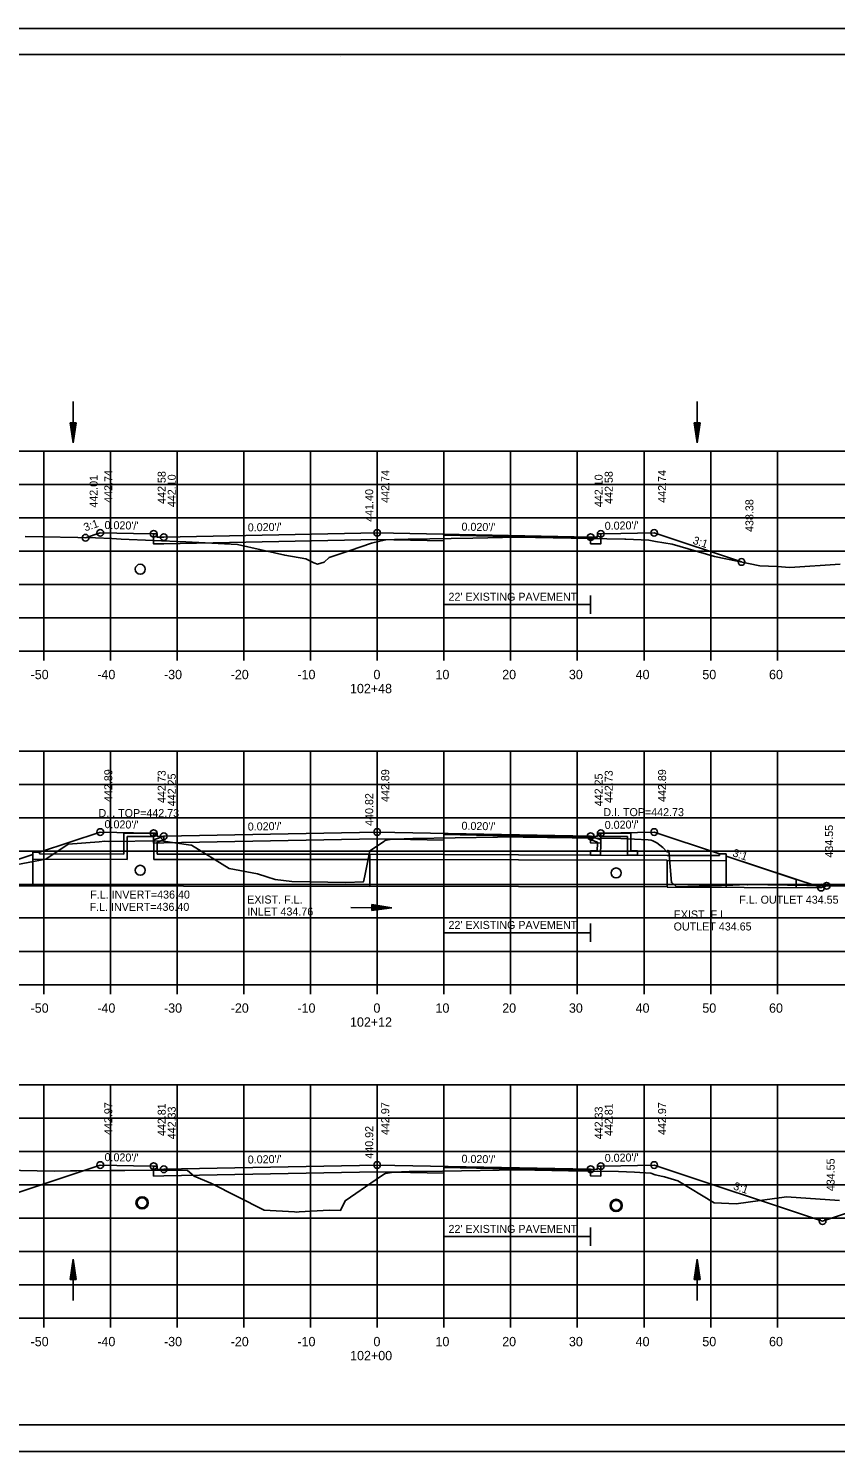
# Model space of a CAD drawing. Extents: x 1538688 to 1540766, y 656250 to 671912.
# Drawn here: x 1538805.9 to 1538926.9, y 656551.2 to 656764.6 of the extents above; entities that cross this region are included whole.
import ezdxf

# ---------------------------------------------------------------- set-up
doc = ezdxf.new("R2010")
doc.units = 0
doc.layers.add('19', color=7, linetype='Continuous')

msp = doc.modelspace()

# ---------------------------------------------------------------- linework, layer by layer
at = {"layer": '19'}
for p, q in [((1538687.78, 656764.57), (1539021.11, 656764.57)), ((1538700.18, 656760.68), (1539016.36, 656760.68)), ((1538852.7, 656760.42), (1538852.7, 656760.42)), ((1538852.7, 656760.42), (1538852.7, 656760.42)), ((1538812.62, 656708.66), (1538812.62, 656702.47)), ((1538906.16, 656708.66), (1538906.16, 656702.47)), ((1538812.17, 656705.47), (1538812.62, 656702.47)), ((1538812.17, 656705.47), (1538813.07, 656705.47)), ((1538812.25, 656705.47), (1538812.62, 656702.97)), ((1538812.33, 656705.47), (1538812.62, 656703.49)), ((1538812.4, 656705.47), (1538812.62, 656703.99)), ((1538812.48, 656705.47), (1538812.62, 656704.5)), ((1538812.55, 656705.47), (1538812.62, 656705)), ((1538813.07, 656705.47), (1538812.62, 656702.47)), ((1538812.77, 656705.47), (1538812.62, 656704.5)), ((1538812.92, 656705.47), (1538812.62, 656703.49)), ((1538813, 656705.47), (1538812.62, 656702.97)), ((1538812.85, 656705.47), (1538812.62, 656703.99)), ((1538812.7, 656705.47), (1538812.62, 656705)), ((1538905.71, 656705.47), (1538906.16, 656702.47)), ((1538905.71, 656705.47), (1538906.61, 656705.47)), ((1538905.79, 656705.47), (1538906.16, 656702.97)), ((1538905.86, 656705.47), (1538906.16, 656703.49)), ((1538905.94, 656705.47), (1538906.16, 656703.99)), ((1538906.02, 656705.47), (1538906.16, 656704.5)), ((1538906.09, 656705.47), (1538906.16, 656705)), ((1538906.61, 656705.47), (1538906.16, 656702.47)), ((1538906.31, 656705.47), (1538906.16, 656704.5)), ((1538906.46, 656705.47), (1538906.16, 656703.49)), ((1538906.54, 656705.47), (1538906.16, 656702.97)), ((1538906.39, 656705.47), (1538906.16, 656703.99)), ((1538906.23, 656705.47), (1538906.16, 656705)), ((1538718.18, 656701.22), (1538998.18, 656701.22)), ((1538808.18, 656671.22), (1538808.18, 656701.22)), ((1538818.18, 656671.22), (1538818.18, 656701.22)), ((1538828.18, 656671.22), (1538828.18, 656701.22)), ((1538838.18, 656671.22), (1538838.18, 656701.22)), ((1538848.18, 656671.22), (1538848.18, 656701.22)), ((1538858.18, 656671.22), (1538858.18, 656701.22)), ((1538868.18, 656671.22), (1538868.18, 656701.22)), ((1538878.18, 656671.22), (1538878.18, 656701.22)), ((1538888.18, 656671.22), (1538888.18, 656701.22)), ((1538898.18, 656671.22), (1538898.18, 656701.22)), ((1538908.18, 656671.22), (1538908.18, 656701.22)), ((1538918.18, 656671.22), (1538918.18, 656701.22)), ((1538718.18, 656696.22), (1538998.18, 656696.22)), ((1538718.18, 656691.22), (1538998.18, 656691.22)), ((1538718.18, 656686.22), (1538998.18, 656686.22)), ((1538718.18, 656681.22), (1538998.18, 656681.22)), ((1538868.17, 656679.59), (1538868.17, 656676.84)), ((1538890.17, 656679.59), (1538890.17, 656676.84)), ((1538890.17, 656678.22), (1538868.17, 656678.22)), ((1538718.18, 656676.22), (1538998.18, 656676.22)), ((1538718.18, 656671.22), (1538998.18, 656671.22)), ((1538718.18, 656671.22), (1538998.18, 656671.22)), ((1538808.18, 656669.82), (1538808.18, 656671.22)), ((1538818.18, 656669.82), (1538818.18, 656671.22)), ((1538828.18, 656669.82), (1538828.18, 656671.22)), ((1538838.18, 656669.82), (1538838.18, 656671.22)), ((1538848.18, 656669.82), (1538848.18, 656671.22)), ((1538858.18, 656669.82), (1538858.18, 656671.22)), ((1538868.18, 656669.82), (1538868.18, 656671.22)), ((1538878.18, 656669.82), (1538878.18, 656671.22)), ((1538888.18, 656669.82), (1538888.18, 656671.22)), ((1538898.18, 656669.82), (1538898.18, 656671.22)), ((1538908.18, 656669.82), (1538908.18, 656671.22)), ((1538918.18, 656669.82), (1538918.18, 656671.22)), ((1538718.18, 656656.22), (1538998.18, 656656.22)), ((1538808.18, 656621.22), (1538808.18, 656656.22)), ((1538818.18, 656621.22), (1538818.18, 656656.22)), ((1538828.18, 656621.22), (1538828.18, 656656.22)), ((1538838.18, 656621.22), (1538838.18, 656656.22)), ((1538848.18, 656621.22), (1538848.18, 656656.22)), ((1538858.18, 656621.22), (1538858.18, 656656.22)), ((1538868.18, 656621.22), (1538868.18, 656656.22)), ((1538878.18, 656621.22), (1538878.18, 656656.22)), ((1538888.18, 656621.22), (1538888.18, 656656.22)), ((1538898.18, 656621.22), (1538898.18, 656656.22)), ((1538908.18, 656621.22), (1538908.18, 656656.22)), ((1538918.18, 656621.22), (1538918.18, 656656.22)), ((1538718.18, 656651.22), (1538998.18, 656651.22)), ((1538718.18, 656646.22), (1538998.18, 656646.22)), ((1538820.18, 656643.95), (1538824.93, 656643.95)), ((1538820.18, 656642.45), (1538820.18, 656643.95)), ((1538820.68, 656642.45), (1538820.68, 656643.45)), ((1538820.68, 656643.45), (1538824.68, 656643.45)), ((1538825.01, 656643.79), (1538824.68, 656643.45)), ((1538826.18, 656643.47), (1538824.68, 656642.95)), ((1538824.68, 656642.45), (1538824.68, 656642.95)), ((1538825.01, 656643.79), (1538824.93, 656643.95)), ((1538826.18, 656642.94), (1538825.18, 656642.6)), ((1538825.18, 656642.45), (1538825.18, 656642.6)), ((1538890.19, 656643.47), (1538891.69, 656642.95)), ((1538890.19, 656642.94), (1538891.19, 656642.6)), ((1538891.19, 656642.45), (1538891.19, 656642.6)), ((1538891.35, 656643.79), (1538891.44, 656643.95)), ((1538891.35, 656643.79), (1538891.69, 656643.45)), ((1538896.19, 656643.95), (1538891.44, 656643.95)), ((1538895.69, 656643.45), (1538891.69, 656643.45)), ((1538891.69, 656642.45), (1538891.69, 656642.95)), ((1538895.69, 656642.45), (1538895.69, 656643.45)), ((1538896.19, 656642.45), (1538896.19, 656643.95)), ((1538718.18, 656641.22), (1538998.18, 656641.22)), ((1538806.58, 656640.75), (1538796.08, 656637.25)), ((1538806.58, 656641.08), (1538806.58, 656636.04)), ((1538807.58, 656641.08), (1538806.58, 656641.08)), ((1538807.58, 656641.08), (1538807.58, 656640.83)), ((1538807.58, 656640.84), (1538820.18, 656640.81)), ((1538808.84, 656640.83), (1538808.84, 656640.83)), ((1538820.18, 656642.45), (1538820.18, 656640.81)), ((1538820.18, 656640.81), (1538820.18, 656640.81)), ((1538820.68, 656642.45), (1538820.68, 656640.01)), ((1538820.68, 656640.8), (1538820.68, 656640.8)), ((1538824.68, 656642.45), (1538824.68, 656640)), ((1538825.18, 656642.46), (1538825.18, 656640.79)), ((1538825.18, 656640.79), (1538825.18, 656640.79)), ((1538825.18, 656640.79), (1538857.1, 656640.77)), ((1538857.1, 656639.98), (1538857.1, 656640.77)), ((1538891.19, 656642.45), (1538891.18, 656641.3)), ((1538891.18, 656640.64), (1538891.18, 656640.64)), ((1538891.69, 656642.45), (1538891.68, 656640.65)), ((1538891.68, 656640.64), (1538891.68, 656640.64)), ((1538895.69, 656642.45), (1538895.68, 656640.63)), ((1538895.68, 656640.63), (1538895.68, 656640.63)), ((1538896.19, 656642.45), (1538896.18, 656641.3)), ((1538896.18, 656640.62), (1538896.18, 656640.62)), ((1538901.65, 656640.61), (1538909.48, 656640.6)), ((1538909.48, 656640.85), (1538910.48, 656640.85)), ((1538909.48, 656640.85), (1538909.48, 656640.6)), ((1538910.48, 656640.85), (1538910.48, 656635.8)), ((1538910.48, 656640.51), (1538920.98, 656637.01)), ((1538806.58, 656640.05), (1538820.68, 656640.01)), ((1538820.68, 656640.01), (1538820.68, 656640.01)), ((1538824.68, 656640), (1538857.1, 656639.98)), ((1538824.68, 656640), (1538824.68, 656640)), ((1538901.65, 656639.82), (1538910.48, 656639.8)), ((1538718.18, 656636.22), (1538998.18, 656636.22)), ((1538792.57, 656636.08), (1538857.1, 656635.93)), ((1538920.98, 656637.01), (1538920.98, 656635.83)), ((1538807.84, 656636.04), (1538807.84, 656636.04)), ((1538901.65, 656635.82), (1538924.73, 656635.76)), ((1538854.21, 656632.81), (1538860.39, 656632.76)), ((1538857.4, 656633.23), (1538857.39, 656632.33)), ((1538857.39, 656632.64), (1538858.37, 656632.78)), ((1538857.39, 656632.71), (1538857.87, 656632.78)), ((1538857.39, 656632.49), (1538859.38, 656632.77)), ((1538857.39, 656632.56), (1538858.88, 656632.77)), ((1538857.39, 656632.33), (1538860.39, 656632.76)), ((1538857.39, 656632.41), (1538859.89, 656632.76)), ((1538857.4, 656633.23), (1538860.39, 656632.76)), ((1538857.4, 656633.16), (1538859.89, 656632.76)), ((1538857.4, 656633.08), (1538859.38, 656632.77)), ((1538857.4, 656633.01), (1538858.88, 656632.77)), ((1538857.4, 656632.93), (1538858.37, 656632.78)), ((1538857.4, 656632.85), (1538857.87, 656632.78)), ((1538718.18, 656631.22), (1538998.18, 656631.22)), ((1538868.17, 656630.39), (1538868.17, 656627.65)), ((1538890.17, 656630.39), (1538890.17, 656627.65)), ((1538890.17, 656629.02), (1538868.17, 656629.02)), ((1538718.18, 656626.22), (1538998.18, 656626.22)), ((1538718.18, 656621.22), (1538998.18, 656621.22)), ((1538718.18, 656621.22), (1538998.18, 656621.22)), ((1538808.18, 656619.82), (1538808.18, 656621.22)), ((1538818.18, 656619.82), (1538818.18, 656621.22)), ((1538828.18, 656619.82), (1538828.18, 656621.22)), ((1538838.18, 656619.82), (1538838.18, 656621.22)), ((1538848.18, 656619.82), (1538848.18, 656621.22)), ((1538858.18, 656619.82), (1538858.18, 656621.22)), ((1538868.18, 656619.82), (1538868.18, 656621.22)), ((1538878.18, 656619.82), (1538878.18, 656621.22)), ((1538888.18, 656619.82), (1538888.18, 656621.22)), ((1538898.18, 656619.82), (1538898.18, 656621.22)), ((1538908.18, 656619.82), (1538908.18, 656621.22)), ((1538918.18, 656619.82), (1538918.18, 656621.22)), ((1538718.18, 656606.22), (1538998.18, 656606.22)), ((1538808.18, 656571.22), (1538808.18, 656606.22)), ((1538818.18, 656571.22), (1538818.18, 656606.22)), ((1538828.18, 656571.22), (1538828.18, 656606.22)), ((1538838.18, 656571.22), (1538838.18, 656606.22)), ((1538848.18, 656571.22), (1538848.18, 656606.22)), ((1538858.18, 656571.22), (1538858.18, 656606.22)), ((1538868.18, 656571.22), (1538868.18, 656606.22)), ((1538878.18, 656571.22), (1538878.18, 656606.22)), ((1538888.18, 656571.22), (1538888.18, 656606.22)), ((1538898.18, 656571.22), (1538898.18, 656606.22)), ((1538908.18, 656571.22), (1538908.18, 656606.22)), ((1538918.18, 656571.22), (1538918.18, 656606.22)), ((1538718.18, 656601.22), (1538998.18, 656601.22)), ((1538718.18, 656596.22), (1538998.18, 656596.22)), ((1538718.18, 656591.22), (1538998.18, 656591.22)), ((1538718.18, 656586.22), (1538998.18, 656586.22)), ((1538868.17, 656584.82), (1538868.17, 656582.08)), ((1538890.17, 656583.45), (1538868.17, 656583.45)), ((1538890.17, 656584.82), (1538890.17, 656582.08)), ((1538718.18, 656581.22), (1538998.18, 656581.22)), ((1538812.17, 656577.05), (1538812.62, 656580.05)), ((1538812.25, 656577.05), (1538812.62, 656579.55)), ((1538812.33, 656577.05), (1538812.62, 656579.04)), ((1538812.4, 656577.05), (1538812.62, 656578.54)), ((1538813.07, 656577.05), (1538812.62, 656580.05)), ((1538812.62, 656573.87), (1538812.62, 656580.05)), ((1538813, 656577.05), (1538812.62, 656579.55)), ((1538812.92, 656577.05), (1538812.62, 656579.04)), ((1538812.85, 656577.05), (1538812.62, 656578.54)), ((1538905.71, 656577.05), (1538906.16, 656580.05)), ((1538905.79, 656577.05), (1538906.16, 656579.55)), ((1538905.86, 656577.05), (1538906.16, 656579.04)), ((1538905.94, 656577.05), (1538906.16, 656578.54)), ((1538906.61, 656577.05), (1538906.16, 656580.05)), ((1538906.16, 656573.87), (1538906.16, 656580.05)), ((1538906.54, 656577.05), (1538906.16, 656579.55)), ((1538906.46, 656577.05), (1538906.16, 656579.04)), ((1538906.39, 656577.05), (1538906.16, 656578.54)), ((1538812.17, 656577.05), (1538813.07, 656577.05)), ((1538812.48, 656577.05), (1538812.62, 656578.03)), ((1538812.55, 656577.05), (1538812.62, 656577.53)), ((1538812.77, 656577.05), (1538812.62, 656578.03)), ((1538812.7, 656577.05), (1538812.62, 656577.53)), ((1538905.71, 656577.05), (1538906.61, 656577.05)), ((1538906.02, 656577.05), (1538906.16, 656578.03)), ((1538906.09, 656577.05), (1538906.16, 656577.53)), ((1538906.31, 656577.05), (1538906.16, 656578.03)), ((1538906.23, 656577.05), (1538906.16, 656577.53)), ((1538718.18, 656576.22), (1538998.18, 656576.22)), ((1538718.18, 656571.22), (1538998.18, 656571.22)), ((1538718.18, 656571.22), (1538998.18, 656571.22)), ((1538808.18, 656569.82), (1538808.18, 656571.22)), ((1538818.18, 656569.82), (1538818.18, 656571.22)), ((1538828.18, 656569.82), (1538828.18, 656571.22)), ((1538838.18, 656569.82), (1538838.18, 656571.22)), ((1538848.18, 656569.82), (1538848.18, 656571.22)), ((1538858.18, 656569.82), (1538858.18, 656571.22)), ((1538868.18, 656569.82), (1538868.18, 656571.22)), ((1538878.18, 656569.82), (1538878.18, 656571.22)), ((1538888.18, 656569.82), (1538888.18, 656571.22)), ((1538898.18, 656569.82), (1538898.18, 656571.22)), ((1538908.18, 656569.82), (1538908.18, 656571.22)), ((1538918.18, 656569.82), (1538918.18, 656571.22)), ((1539016.36, 656555.22), (1538700.18, 656555.22)), ((1538687.78, 656551.24), (1539021.11, 656551.24))]:
    msp.add_line(p, q, dxfattribs=at)
msp.add_lwpolyline([(1538687.77, 656764.57), (1539021.11, 656764.57), (1539021.11, 656551.24), (1538687.77, 656551.24)], close=True, dxfattribs=at)
for points in [[(1538805.4, 656688.39), (1538815.96, 656688.2), (1538818.4, 656688.12), (1538819.79, 656688.02), (1538829.51, 656687.63), (1538837.26, 656687.21), (1538844.31, 656685.6), (1538847.5, 656685.07), (1538848.69, 656684.45), (1538849.25, 656684.28), (1538850.23, 656684.58), (1538850.98, 656685.26), (1538854.12, 656686.29), (1538857.31, 656687.42), (1538858.55, 656687.71), (1538859.45, 656687.93), (1538860.75, 656687.94), (1538862.8, 656688), (1538872.53, 656688.17), (1538879.21, 656688.31), (1538895.3, 656688.02), (1538895.41, 656688.02), (1538895.44, 656688.02), (1538898.88, 656687.88), (1538899.91, 656687.66), (1538902.42, 656687.27), (1538908.75, 656685.43), (1538915.53, 656684.02), (1538918.15, 656683.89), (1538920.05, 656683.76), (1538927.58, 656684.27)], [(1538814.47, 656688.23), (1538816.67, 656688.96), (1538821.67, 656688.86), (1538824.67, 656688.8), (1538825.17, 656688.8), (1538825.18, 656688.3), (1538826.18, 656688.32), (1538858.18, 656688.96), (1538890.18, 656688.32), (1538891.18, 656688.3), (1538891.19, 656688.8), (1538891.69, 656688.8), (1538894.69, 656688.86), (1538899.69, 656688.96), (1538912.78, 656684.59)], [(1538891.69, 656688.8), (1538891.69, 656687.3), (1538890.18, 656687.32), (1538890.18, 656687.32), (1538890.18, 656688.15), (1538868.18, 656688.59), (1538868.18, 656687.76), (1538858.18, 656687.96), (1538826.18, 656687.32), (1538824.67, 656687.3), (1538824.67, 656688.8)], [(1538803.23, 656639.06), (1538808.5, 656640.02), (1538811.84, 656642.27), (1538816.52, 656642.64), (1538817.34, 656642.72), (1538817.94, 656642.71), (1538825.81, 656642.77), (1538830.24, 656642.13), (1538830.33, 656642.12), (1538836.01, 656638.66), (1538840.26, 656637.84), (1538841.62, 656637.4), (1538842.9, 656636.97), (1538845.39, 656636.7), (1538853.47, 656636.54), (1538856.11, 656636.63), (1538856.34, 656637.54), (1538857.1, 656641.31), (1538859.26, 656642.76), (1538859.33, 656642.82), (1538860.37, 656643.03), (1538860.45, 656643.05), (1538860.93, 656643.06), (1538863.52, 656643.15), (1538876.22, 656643.32), (1538879.24, 656643.37), (1538880.08, 656643.35), (1538894.7, 656643.13), (1538898.78, 656642.93), (1538899.23, 656642.9), (1538899.48, 656642.78), (1538900.11, 656642.51), (1538900.99, 656641.77), (1538901.65, 656641.09), (1538901.74, 656641.36), (1538901.89, 656641.28), (1538902.28, 656636.54), (1538902.37, 656636.53), (1538903.07, 656635.9), (1538911.47, 656636.15), (1538913.54, 656636.23), (1538913.69, 656636.2), (1538913.85, 656636.23), (1538925.48, 656636.05), (1538931.27, 656636.01)], [(1538807.58, 656641.08), (1538816.67, 656644.11), (1538821.67, 656644.01), (1538824.67, 656643.95), (1538825.17, 656643.95), (1538825.18, 656643.45), (1538826.18, 656643.47), (1538858.18, 656644.11), (1538890.18, 656643.47), (1538891.18, 656643.45), (1538891.19, 656643.95), (1538891.69, 656643.95), (1538894.69, 656644.01), (1538899.69, 656644.11), (1538909.48, 656640.85)], [(1538891.69, 656643.95), (1538891.69, 656642.45), (1538890.18, 656642.47), (1538890.18, 656642.47), (1538890.18, 656643.3), (1538868.18, 656643.74), (1538868.18, 656642.91), (1538858.18, 656643.11), (1538826.18, 656642.47), (1538824.67, 656642.45), (1538824.67, 656643.95)], [(1538826.18, 656642.94), (1538826.18, 656643.47)], [(1538890.19, 656642.94), (1538890.19, 656643.47)], [(1538783.68, 656639.04), (1538792.57, 656636.08), (1538806.58, 656640.75)], [(1538901.65, 656640.61), (1538857.1, 656640.77)], [(1538891.18, 656641.3), (1538890.18, 656641.3), (1538890.18, 656640.65), (1538891.68, 656640.65)], [(1538896.18, 656641.3), (1538897.18, 656641.3), (1538897.18, 656640.63), (1538895.68, 656640.63), (1538895.68, 656641.3), (1538895.68, 656641.3)], [(1538910.48, 656640.51), (1538924.72, 656635.77), (1538925.56, 656636.05)], [(1538901.66, 656639.87), (1538857.1, 656639.98)], [(1538857.1, 656639.98), (1538857.1, 656635.98), (1538901.65, 656635.87), (1538901.66, 656639.87)], [(1538768.09, 656594.16), (1538792.33, 656586.08), (1538816.67, 656594.19), (1538821.67, 656594.09), (1538824.67, 656594.03), (1538825.17, 656594.03), (1538825.18, 656593.53), (1538826.18, 656593.55), (1538858.18, 656594.19), (1538890.18, 656593.55), (1538891.18, 656593.53), (1538891.19, 656594.03), (1538891.69, 656594.03), (1538894.69, 656594.09), (1538899.69, 656594.19), (1538924.95, 656585.77), (1538933.19, 656588.51)], [(1538794.49, 656593.55), (1538809.77, 656593.27), (1538812.18, 656593.34), (1538813.17, 656593.33), (1538818.28, 656593.38), (1538818.79, 656593.39), (1538820.33, 656593.38), (1538829.06, 656593.41), (1538829.75, 656593.36), (1538830.75, 656592.54), (1538833.25, 656591.48), (1538841.25, 656587.43), (1538845.77, 656587.16), (1538846.09, 656587.13), (1538846.48, 656587.19), (1538850.1, 656587.36), (1538851.04, 656587.42), (1538852.69, 656587.38), (1538853.37, 656588.82), (1538858.01, 656592.03), (1538859.28, 656592.87), (1538859.41, 656592.9), (1538860.61, 656593.13), (1538862.99, 656593.21), (1538863.8, 656593.24), (1538867.97, 656593.29), (1538879.29, 656593.49), (1538886.85, 656593.34), (1538894.37, 656593.23), (1538896.73, 656593.11), (1538899.22, 656592.97), (1538899.87, 656592.7), (1538901.02, 656592.49), (1538901.24, 656592.44), (1538903.24, 656591.8), (1538908.71, 656588.5), (1538912.01, 656588.36), (1538919.55, 656589.4), (1538927.48, 656588.87)], [(1538891.69, 656594.03), (1538891.69, 656592.53), (1538890.18, 656592.55), (1538890.18, 656592.55), (1538890.18, 656593.38), (1538868.18, 656593.82), (1538868.18, 656592.99), (1538858.18, 656593.19), (1538826.18, 656592.55), (1538824.67, 656592.53), (1538824.67, 656594.03)]]:
    msp.add_lwpolyline(points, dxfattribs=at)
for centre, radius in [((1538816.67, 656688.96), 0.5), ((1538858.18, 656688.96), 0.5), ((1538899.69, 656688.96), 0.5), ((1538814.47, 656688.23), 0.5), ((1538824.67, 656688.8), 0.5), ((1538826.18, 656688.32), 0.5), ((1538890.18, 656688.32), 0.5), ((1538891.69, 656688.8), 0.5), ((1538822.66, 656683.5), 0.75), ((1538912.78, 656684.59), 0.5), ((1538816.67, 656644.11), 0.5), ((1538858.18, 656644.11), 0.5), ((1538899.69, 656644.11), 0.5), ((1538824.67, 656643.95), 0.5), ((1538826.18, 656643.47), 0.5), ((1538890.18, 656643.47), 0.5), ((1538891.69, 656643.95), 0.5), ((1538822.66, 656638.37), 0.75), ((1538894, 656637.97), 0.75), ((1538924.72, 656635.77), 0.5), ((1538925.56, 656636.05), 0.5), ((1538816.67, 656594.19), 0.5), ((1538824.67, 656594.03), 0.5), ((1538826.18, 656593.55), 0.5), ((1538858.18, 656594.19), 0.5), ((1538890.18, 656593.55), 0.5), ((1538891.69, 656594.03), 0.5), ((1538899.69, 656594.19), 0.5), ((1538822.93, 656588.52), 0.917), ((1538822.93, 656588.52), 0.75), ((1538894, 656588.13), 0.917), ((1538894, 656588.13), 0.75), ((1538924.95, 656585.77), 0.5)]:
    msp.add_circle(centre, radius, dxfattribs=at)

# ---------------------------------------------------------------- texts
for s, rotation, p in [('442.74', 90, (1538818.47, 656693.46)), ('442.58', 90, (1538826.47, 656693.3)), ('442.74', 90, (1538859.98, 656693.46)), ('442.58', 90, (1538893.49, 656693.3)), ('442.74', 90, (1538901.49, 656693.46)), ('442.01', 90, (1538816.27, 656692.73)), ('442.10', 90, (1538827.98, 656692.82)), ('442.10', 90, (1538891.98, 656692.82)), ('441.40', 90, (1538857.58, 656690.62)), ('438.38', 90, (1538914.58, 656689.09)), ('3:1', 18.4349, (1538814.41, 656689.17)), ("0.020'/'", 358.8542, (1538817.3, 656689.54)), ("0.020'/'", 1.1458, (1538838.79, 656689.17)), ("0.020'/'", 358.8542, (1538870.81, 656689.3)), ("0.020'/'", 1.1458, (1538892.3, 656689.41)), ('3:1', 341.5651, (1538905.39, 656687.35)), ('442.89', 90, (1538818.47, 656648.61)), ('442.73', 90, (1538826.47, 656648.45)), ('442.89', 90, (1538859.98, 656648.61)), ('442.73', 90, (1538893.49, 656648.45)), ('442.89', 90, (1538901.49, 656648.61)), ('442.25', 90, (1538827.98, 656647.97)), ('442.25', 90, (1538891.98, 656647.97)), ('440.82', 90, (1538857.58, 656645.03)), ("0.020'/'", 358.8542, (1538817.3, 656644.7)), ("0.020'/'", 1.1458, (1538838.79, 656644.32)), ("0.020'/'", 358.8542, (1538870.81, 656644.46)), ("0.020'/'", 1.1458, (1538892.3, 656644.56)), ('434.55', 90, (1538926.52, 656640.27)), ('3:1', 341.5651, (1538911.36, 656640.51)), ('442.97', 90, (1538818.47, 656598.69)), ('442.81', 90, (1538826.47, 656598.53)), ('442.33', 90, (1538827.98, 656598.05)), ('442.97', 90, (1538859.98, 656598.69)), ('442.33', 90, (1538891.98, 656598.05)), ('442.81', 90, (1538893.49, 656598.53)), ('442.97', 90, (1538901.49, 656598.69)), ('440.92', 90, (1538857.58, 656595.14)), ("0.020'/'", 358.8542, (1538817.3, 656594.78)), ("0.020'/'", 1.1458, (1538838.79, 656594.4)), ("0.020'/'", 358.8542, (1538870.81, 656594.54)), ("0.020'/'", 1.1458, (1538892.3, 656594.64)), ('434.55', 90, (1538926.75, 656590.27)), ('3:1', 341.5651, (1538911.48, 656590.55))]:
    msp.add_text(s, height=1.2, rotation=rotation, dxfattribs=at).set_placement(p)
for s, height, p in [("22' EXISTING PAVEMENT", 1.2, (1538868.87, 656678.78)), ('-50', 1.4, (1538806.22, 656667.02)), ('-40', 1.4, (1538816.22, 656667.02)), ('-30', 1.4, (1538826.22, 656667.02)), ('-20', 1.4, (1538836.22, 656667.02)), ('-10', 1.4, (1538846.22, 656667.02)), ('0', 1.4, (1538857.62, 656667.02)), ('10', 1.4, (1538866.92, 656667.02)), ('20', 1.4, (1538876.92, 656667.02)), ('30', 1.4, (1538886.92, 656667.02)), ('40', 1.4, (1538896.92, 656667.02)), ('50', 1.4, (1538906.92, 656667.02)), ('60', 1.4, (1538916.92, 656667.02)), ('102+48', 1.4, (1538854.1, 656664.92)), ('D.I. TOP=442.73', 1.2, (1538816.4, 656646.35)), ('D.I. TOP=442.73', 1.2, (1538892.08, 656646.49)), ('F.L. INVERT=436.40', 1.2, (1538815.16, 656634.13)), ('EXIST. F.L.', 1.2, (1538838.69, 656633.39)), ('F.L. OUTLET 434.55', 1.2, (1538912.45, 656633.37)), ('F.L. INVERT=436.40', 1.2, (1538815.07, 656632.29)), ('INLET 434.76', 1.2, (1538838.69, 656631.59)), ('EXIST. F.L.', 1.2, (1538902.62, 656631.15)), ("22' EXISTING PAVEMENT", 1.2, (1538868.87, 656629.58)), ('OUTLET 434.65', 1.2, (1538902.62, 656629.35)), ('-50', 1.4, (1538806.22, 656617.02)), ('-40', 1.4, (1538816.22, 656617.02)), ('-30', 1.4, (1538826.22, 656617.02)), ('-20', 1.4, (1538836.22, 656617.02)), ('-10', 1.4, (1538846.22, 656617.02)), ('0', 1.4, (1538857.62, 656617.02)), ('10', 1.4, (1538866.92, 656617.02)), ('20', 1.4, (1538876.92, 656617.02)), ('30', 1.4, (1538886.92, 656617.02)), ('40', 1.4, (1538896.92, 656617.02)), ('50', 1.4, (1538906.92, 656617.02)), ('60', 1.4, (1538916.92, 656617.02)), ('102+12', 1.4, (1538854.1, 656614.92)), ("22' EXISTING PAVEMENT", 1.2, (1538868.87, 656584.01)), ('-50', 1.4, (1538806.22, 656567.02)), ('-40', 1.4, (1538816.22, 656567.02)), ('-30', 1.4, (1538826.22, 656567.02)), ('-20', 1.4, (1538836.22, 656567.02)), ('-10', 1.4, (1538846.22, 656567.02)), ('0', 1.4, (1538857.62, 656567.02)), ('10', 1.4, (1538866.92, 656567.02)), ('20', 1.4, (1538876.92, 656567.02)), ('30', 1.4, (1538886.92, 656567.02)), ('40', 1.4, (1538896.92, 656567.02)), ('50', 1.4, (1538906.92, 656567.02)), ('60', 1.4, (1538916.92, 656567.02)), ('102+00', 1.4, (1538854.12, 656564.92))]:
    msp.add_text(s, height=height, dxfattribs=at).set_placement(p)

doc.saveas('drawing.dxf')
